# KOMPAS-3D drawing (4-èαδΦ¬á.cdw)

Referenced files in E:\Моя музыка\VVV\Мои документы\О.О.К.М\: Чертеж крышки.cdw
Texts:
  Крышка
  125 1 126 1 127 1 128 0 50 1|SPDS|125 1 126 1 127 1 128 0 50 1
  129 1 130 1 131 1 132 0 50 1|SPDS|129 1 130 1 131 1 132 0 50 1
  1. Литейные уклоны- 3 , литейные радиусы- 3...5мм.
  Symbol type B
  2. Неуказанные предельные откланения размеров: h14, H14,  IT14 2 .
  Ra 3,2
  Ra 6,3
  Крышка-
  СЧ15 ГОСТ 1412-88
  ТФ ДГТУ
Dimensions and other numbers on the sheet: 0,75; 1; 3; 190; 6; 4; 20; 2; 160; 120; 220; 0.020; 0,060; 200; 12; 6 отв.; 1:1; 0,82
